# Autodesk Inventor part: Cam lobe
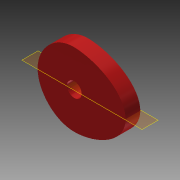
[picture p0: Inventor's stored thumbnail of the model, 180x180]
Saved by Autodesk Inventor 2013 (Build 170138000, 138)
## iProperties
Created: 2008-06
Part Number: Cam lobe
Document SubType Name: Modeling
Designer: tangg
Density: 7.75 g/cm^3
Mass: 5.71787 g
Surface Area: 26.2129 cm^2
Volume: 5.71787 cm^3
Stock Number: Cam lobe
Material: Stainless Steel, 440C
Author: tangg
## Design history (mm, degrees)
sketch "Sketch1"
  geometry: L1 (-0.008, 11.43)-(-0.008, -11.43); L2 (-0.008, 0.008)-(15.875, -15.875); L3 (0, 0)-(13.517, 13.517); L4 (-0.008, 0.008)-(-14.375, 14.375); L5 (0, 0)-(-13.139, -13.139); L6 (22.225, 3.829)-(22.225, -3.829); L7 (4.981, -15.875)-(-4.981, -15.875); C1 r 3.175 at (0, 0); A1 r 10.081 centre (12.144, 0) between (21.789, -2.931) and (21.789, 2.931); A2 r 19.362 centre (0, 3.487) between (-3.903, -15.478) and (3.903, -15.478); 8 further points
  constraints: 14 end point, 5 midpoint, 3 centre point, 3 point on line, 3 vertical, 2 horizontal, 2 point on circle, 1 coincident, 12 other
  dimensions: "d0" = 6.35 diameter of C1; "d7" = 45 deg angle of L1 L2; "d8" = 45 deg angle of L1 L3; "d9" = 45 deg angle of L5 L1; "d10" = 45 deg angle of L4 L1
extrude "Extrusion1" new body sketch "Sketch1" distance "d1" = 6.35; taper "d2" = 0 deg
sketch "Sketch4"
  geometry: 1 further point
sketch "Sketch5"
  geometry: 1 further point
body "Solid1"
